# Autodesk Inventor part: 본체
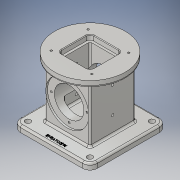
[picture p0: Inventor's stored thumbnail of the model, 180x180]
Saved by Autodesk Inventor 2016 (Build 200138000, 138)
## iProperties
Created: 2021-05
Part Number: 본체
Material: 알루미늄 6061
Document SubType Name: Modeling
Designer: Windows7
Density: 2.7 g/cm^3
Appearance: 알루미늄 - 평지
Mass: 1250.5 g
Surface Area: 898.644 cm^2
Volume: 463.149 cm^3
Author: Windows7
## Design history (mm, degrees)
sketch "스케치1"
  geometry: L1 (62.5, -62.5)-(-62.5, -62.5); L2 (-62.5, -62.5)-(-62.5, 62.5); L3 (-62.5, 62.5)-(62.5, 62.5); L4 (62.5, 62.5)-(62.5, -62.5); L5 (62.5, -62.5)-(-62.5, 62.5); L6 (-62.5, -62.5)-(62.5, 62.5); 1 further point
  constraints: 12 end point, 2 midpoint, 2 parallel, 1 horizontal, 1 perpendicular
  dimensions: "d0" = 125 distance of L2.end L3.end; "d1" = 125 distance of L1.end L2.end
extrude "돌출1" new body sketch "스케치1" distance "d2" = 10; taper "d3" = 0 deg
sketch "스케치2"
  geometry: L1 (-37, -37)-(37, -37); L2 (37, -37)-(37, 37); L3 (37, 37)-(-37, 37); L4 (-37, 37)-(-37, -37); L5 (-37, -37)-(37, 37); L6 (37, -37)-(-37, 37); 1 further point
  constraints: 12 end point, 2 midpoint, 2 parallel, 1 horizontal, 1 perpendicular
  dimensions: "d4" = 74 distance of L3.end L2.end; "d5" = 74 distance of L1.end L2.end
extrude "돌출2" join sketch "스케치2" distance "d6" = 88; taper "d7" = 0 deg
sketch "스케치3"
  geometry: C1 r 57.5 at (0, 0); 1 further point
  constraints: 1 centre point, 1 coincident
  dimensions: "d8" = 115 diameter of C1
extrude "돌출3" join sketch "스케치3" distance "d9" = 10; taper "d10" = 0 deg
sketch "스케치4"
  geometry: C1 r 28 at (0, 0); 1 further point
  constraints: 1 centre point, 1 coincident
  dimensions: "d11" = 56 diameter of C1
extrude "돌출4" cut sketch "스케치4" distance "d12" = 18; taper "d13" = -10 deg
sketch "스케치5"
  geometry: L1 (-26, 26)-(26, 26); L2 (26, 26)-(26, -26); L3 (26, -26)-(-26, -26); L4 (-26, -26)-(-26, 26); L5 (-26, 26)-(26, -26); L6 (26, 26)-(-26, -26); 1 further point
  constraints: 12 end point, 2 midpoint, 2 parallel, 1 horizontal, 1 perpendicular
  dimensions: "d14" = 52 distance of L2.end L3.end; "d15" = 52 distance of L1.end L2.end
extrude "돌출5" cut sketch "스케치5" distance "d16" = 8; taper "d17" = 0 deg
sketch "스케치6"
  geometry: L1 (-22, 22)-(22, 22); L2 (22, 22)-(22, -22); L3 (22, -22)-(-22, -22); L4 (-22, -22)-(-22, 22); L5 (-22, 22)-(22, -22); L6 (22, 22)-(-22, -22); 1 further point
  constraints: 12 end point, 2 midpoint, 2 parallel, 1 horizontal, 1 perpendicular
  dimensions: "d18" = 44 distance of L2.end L3.end; "d19" = 44 distance of L1.end L2.end
extrude "돌출6" cut sketch "스케치6" distance "d20" = 74; taper "d21" = 0 deg
sketch "스케치7"
  geometry: L1 (99.5, -10)-(-25.5, -10) reference; C1 r 35 at (37, 44); 2 further points
  constraints: 1 centre point, 1 midpoint, 1 vertical alignment
  dimensions: "d22" = 70 diameter of C1; "d23" = 54 distance from line of L1 C1.centre
extrude "돌출7" cut sketch "스케치7" distance "d24" = 3; taper "d25" = 0 deg
sketch "스케치8"
  geometry: C1 r 35 at (0, 0) reference; C2 r 24 at (0, 0); 1 further point
  constraints: 1 centre point, 1 coincident
  dimensions: "d26" = 48 diameter of C2
extrude "돌출8" cut sketch "스케치8" distance "d27" = 50; taper "d28" = 0 deg
sketch "스케치9" dims "d29" = 58
  geometry: L1 (62.5, -54)-(-62.5, -54) reference; A1 r 24 centre (0, 0) between (22, 9.592) and (-22, 9.592) reference; 4 further points
  constraints: 2 vertical alignment, 1 coincident, 1 midpoint, 2 other
hole "구멍1" sketch "스케치9" at (0, 29) diameter "d30" = 3.242; stored, may be unused: countersink angle "d34" = 90 deg, drill point angle "d36" = 118 deg; dims "d31" = 8, "d32" = 4, "d33" = 2, "d35" = 10
sketch "스케치10"
  geometry: 2 further points
  dimensions: "d40" = 33 horizontal distance of point (-33, 30) point (0, 0); "d41" = 30 vertical distance of point (-33, 30) point (0, 0)
hole "구멍2" sketch "스케치10" at (-33, 30) diameter "d42" = 3.242; stored, may be unused: countersink angle "d46" = 90 deg, drill point angle "d48" = 118 deg; dims "d43" = 8, "d44" = 4, "d45" = 2, "d47" = 10
fillet "모깎기1" dims "d55" = 12
sketch "스케치12"
  geometry: C1 r 4.5 at (-50.5, 50.5); C2 r 4.5 at (-50.5, -50.5); C3 r 4.5 at (50.5, 50.5); C4 r 4.5 at (50.5, -50.5); A1 r 12 centre (-50.5, 50.5) between (-50.5, 62.5) and (-62.5, 50.5) reference; A2 r 12 centre (-50.5, -50.5) between (-62.5, -50.5) and (-50.5, -62.5) reference; A3 r 12 centre (50.5, 50.5) between (62.5, 50.5) and (50.5, 62.5) reference; A4 r 12 centre (50.5, -50.5) between (50.5, -62.5) and (62.5, -50.5) reference; 1 further point
  constraints: 4 centre point, 4 coincident
  dimensions: "d56" = 9 diameter of C1; "d57" = 9 diameter of C2; "d58" = 9 diameter of C3; "d59" = 9 diameter of C4
extrude "돌출9" cut sketch "스케치12" distance "d60" = 10; taper "d61" = 0 deg
sketch "스케치13"
  geometry: 2 further points
  constraints: 1 vertical alignment, 1 other
  dimensions: "d62" = 55 distance of point (0, 0) point (0, -55)
feature "엠보싱1" sketch "스케치13" dims "d0" = 125, "d1" = 125, "d63" = 0.5, "d64" = 0
fillet "모깎기2" dims "d65" = 3
fillet "모깎기3" dims "d66" = 6
fillet "모깎기4" dims "d67" = 3
fillet "모깎기5" dims "d68" = 3
fillet "모깎기6" dims "d69" = 3
fillet "모깎기7" dims "d70" = 3
fillet "모깎기8" dims "d71" = 3
fillet "모깎기9" dims "d72" = 3
chamfer "모따기1" distance "d73" = 1; stored, may be unused: second distance "d74" = 2, angle "d75" = 45 deg
sketch "스케치14"
  geometry: L1 (84.5, -13)-(-16.5, -13) reference; 5 further points
  constraints: 2 midpoint, 2 vertical alignment
  dimensions: "d76" = 37 distance from line of L1 point (34, 24); "d77" = 43 distance of point (34, 24) point (34, 67)
hole "구멍3" sketch "스케치14" at (34, 67), (34, 24) diameter "d78" = 4.134; stored, may be unused: countersink angle "d82" = 90 deg, drill point angle "d84" = 118 deg; dims "d79" = 15, "d80" = 4, "d81" = 2, "d83" = 15
node "솔리드1"
pattern_circular "원형 패턴1" dims angle "d38" = 360 deg
mirror "대칭1"
pattern_linear "직사각형 패턴1" dims "d51" = 66
mirror "대칭2"
